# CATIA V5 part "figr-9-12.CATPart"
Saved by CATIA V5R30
Part number: Part2
Bounding box of the stored display mesh (mm): x -96.75 to 0, y -83.031 to 83.031, z -58.031 to 58.031
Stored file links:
  D:\PROJECTS\CATIA V56R 2020\Resources\Parts File\c09_catia_v5_6r2020_prt\figr-9-12.CATPart
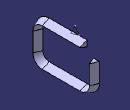
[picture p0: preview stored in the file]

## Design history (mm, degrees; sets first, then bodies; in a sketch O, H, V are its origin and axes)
Body1 (main body)
  Sketch1 on yz-plane, origin (0, 0, 0), H (0, 1, 0), V (0, 0, 1)
    point P1 (-75, 50)
    line L1 (-50, 50) -> (50, 50)
    line L2 (75, 25) -> (75, -25)
    line L3 (50, -50) -> (-50, -50)
    line L4 (-75, -25) -> (-75, 25)
    point P2 (75, 50)
    point P3 (75, -50)
    arc A1 centre (-50, 25) radius 25 from (-50, 50) to (-75, 25) ccw
    arc A2 centre (-50, -25) radius 25 from (-50, -50) to (-75, -25) cw
    arc A3 centre (50, -25) radius 25 from (50, -50) to (75, -25) ccw
    distance V L4 = 75
    distance H L1 = 50
    distance P1 P2 = 150
    radius A1 = 25
    radius A2 = 25
    distance P2 P3 = 100
    radius A3 = 25
    horizontal: L1 H, L3 H
    vertical: L2 V, L4 V
    coincidence: L1 P1, L4 P1, L3 P3, L2 P3, L2 P2, L1 P2
    tangency: A1 L1, A1 L4, A2 L3, A2 L4, A3 L3, A3 L2
  Plane1: type Angle, RefPlane yz-plane, Direction Sketch1.V, Angle 31
  Plane2: type Offset, RefPlane Plane1, Offset -108
  Sketch2 on Plane2, origin (-92.5741, -55.6241, 0), H (-0.515, 0.8572, 0), V (0, 0, 1)
    line L1 (0, 0) -> (-8.0309, -18.5626)
    line L2 (-8.0309, -18.5626) -> (8.1085, -18.5626)
    line L3 (8.1085, -18.5626) -> (0, 0)
    horizontal: L2 H
  Rib1: profile Sketch2, centre curve Sketch1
